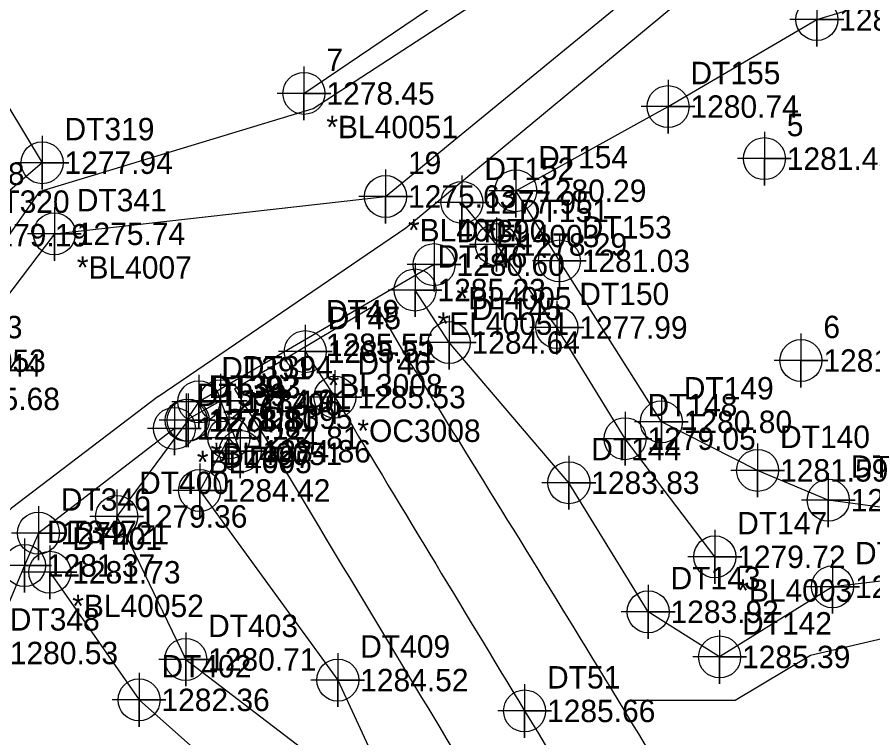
# Model space of a CAD drawing. Extents: x 1394009 to 1394411, y 957864 to 958364.
# Drawn here: x 1394188.2 to 1394283.7, y 958034.4 to 958114.8 of the extents above; entities that cross this region are included whole.
import ezdxf

# ---------------------------------------------------------------- set-up
doc = ezdxf.new("R2010")
doc.units = 0
for name, color, linetype in [('Exist DTM Breakline', 7, 'Continuous'), ('Exist DTM Breakline Cogo Comment', 7, 'Continuous'), ('Exist DTM Breakline Cogo Elevation', 7, 'Continuous'), ('Exist DTM Breakline Cogo Number', 7, 'Continuous'), ('Exist DTM Breakline Cogo Point CELL', 7, 'Continuous'), ('Exist DTM Breakline Underwater', 7, 'Continuous'), ('Exist DTM Breakline Underwater Cogo Comment', 7, 'Continuous'), ('Exist DTM Breakline Underwater Cogo Elevation', 7, 'Continuous'), ('Exist DTM Breakline Underwater Cogo Number', 7, 'Continuous'), ('Exist DTM Breakline Underwater Cogo Point CELL', 7, 'Continuous'), ('Exist DTM Crownline', 7, 'Continuous'), ('Exist DTM Drainline', 7, 'Continuous'), ('Exist DTM Drainline Cogo Comment', 7, 'Continuous'), ('Exist DTM Drainline Cogo Elevation', 7, 'Continuous'), ('Exist DTM Drainline Cogo Number', 7, 'Continuous'), ('Exist DTM Drainline Cogo Point CELL', 7, 'Continuous'), ('Exist DTM Regular Point Cogo Elevation', 7, 'Continuous'), ('Exist Hydro Stream or Body of Water', 7, 'Continuous'), ('Exist Roads EOP', 7, 'Continuous'), ('Exist Roads Soil', 7, 'Continuous'), ('Exist Structure Minor Culvert Topo', 7, 'Continuous'), ('Exist Structure Minor Culvert Topo Terminator', 7, 'Continuous'), ('Exist Structure Minor Footbridge', 7, 'Continuous'), ('Exist Structure Minor Footbridge Terminator', 7, 'Continuous'), ('PH Exist DTM NCFMP LIDAR Elevation Point', 7, 'Continuous'), ('Raster_Level_0', 7, 'Continuous')]:
    doc.layers.add(name, color=color, linetype=linetype)

msp = doc.modelspace()

# ---------------------------------------------------------------- linework, layer by layer
at = {"layer": 'Exist DTM Breakline'}
for points in [[(1394078.4815, 958267.2528), (1394082.9126, 958267.3867), (1394095.8187, 958243.0525), (1394113.4272, 958206.3553), (1394134.4907, 958171.1858), (1394155.1759, 958139.8204), (1394165.1856, 958129.7757), (1394177.2665, 958121.2673), (1394190.9858, 958098.52), (1394181.5225, 958090.4285), (1394174.2125, 958080.1878)], [(1394220.2003, 958106.2482), (1394237.6839, 958118.114), (1394249.3757, 958131.9705), (1394256.7573, 958157.1006), (1394253.8139, 958176.5432), (1394241.3147, 958204.2553), (1394238.5837, 958222.5694)], [(1394338.5703, 958071.7873), (1394311.6428, 958061.939), (1394296.3165, 958058.5038), (1394278.7037, 958060.8799), (1394270.8162, 958064.205), (1394260.0757, 958069.6149), (1394248.6938, 958087.5642), (1394243.8244, 958095.3933), (1394260.8199, 958104.7758), (1394277.4189, 958114.4853), (1394301.9851, 958121.8746)], [(1394234.7161, 958087.1493), (1394208.4745, 958071.86), (1394207.051, 958069.7897), (1394210.8783, 958071.9618), (1394213.0858, 958066.3393), (1394211.818, 958067.823), (1394208.5647, 958061.9703), (1394223.9737, 958040.8216), (1394237.157, 958012.3346), (1394253.5006, 957985.8224), (1394267.2603, 957974.749), (1394288.6525, 957938.4432), (1394308.2436, 957898.2998)], [(1394314.9529, 958057.597), (1394299.8393, 958053.6184), (1394279.177, 958051.2301), (1394266.5791, 958043.3997), (1394258.6023, 958048.4386), (1394249.7488, 958062.8318), (1394236.4026, 958078.4617), (1394232.5982, 958084.3218)], [(1394207.2831, 958069.7981), (1394199.3051, 958059.0705), (1394207.0076, 958043.1259), (1394225.1737, 958029.2554), (1394237.0033, 958012.304)], [(1394205.7466, 958068.8917), (1394190.5711, 958057.2067), (1394189.0222, 958053.5957), (1394184.8806, 958043.8407), (1394186.4655, 958021.4355), (1394191.8774, 958003.2638), (1394213.2872, 957998.1706), (1394228.4733, 957975.4923), (1394239.8888, 957946.4968), (1394241.0497, 957903.4511)], [(1394191.8454, 958052.8419), (1394201.7992, 958038.6118), (1394220.6022, 958021.9205), (1394235.2523, 958009.2773), (1394253.0852, 957986.3641)]]:
    msp.add_lwpolyline(points, dxfattribs=at)
at = {"layer": 'Exist DTM Breakline Cogo Point CELL'}
for points in [[(1394277.4189, 958117.4853), (1394277.4189, 958111.4853), (1394277.4189, 958114.4853), (1394280.4189, 958114.4853), (1394274.4189, 958114.4853)], [(1394220.2003, 958109.2482), (1394220.2003, 958103.2482), (1394220.2003, 958106.2482), (1394223.2003, 958106.2482), (1394217.2003, 958106.2482)], [(1394260.8199, 958107.7758), (1394260.8199, 958101.7758), (1394260.8199, 958104.7758), (1394263.8199, 958104.7758), (1394257.8199, 958104.7758)], [(1394190.9858, 958101.52), (1394190.9858, 958095.52), (1394190.9858, 958098.52), (1394193.9858, 958098.52), (1394187.9858, 958098.52)], [(1394243.8244, 958098.3933), (1394243.8244, 958092.3933), (1394243.8244, 958095.3933), (1394246.8244, 958095.3933), (1394240.8244, 958095.3933)], [(1394234.7161, 958090.1493), (1394234.7161, 958084.1493), (1394234.7161, 958087.1493), (1394237.7161, 958087.1493), (1394231.7161, 958087.1493)], [(1394248.6938, 958090.5642), (1394248.6938, 958084.5642), (1394248.6938, 958087.5642), (1394251.6938, 958087.5642), (1394245.6938, 958087.5642)], [(1394232.5982, 958087.3218), (1394232.5982, 958081.3218), (1394232.5982, 958084.3218), (1394235.5982, 958084.3218), (1394229.5982, 958084.3218)], [(1394236.4026, 958081.4617), (1394236.4026, 958075.4617), (1394236.4026, 958078.4617), (1394239.4026, 958078.4617), (1394233.4026, 958078.4617)], [(1394208.4745, 958074.86), (1394208.4745, 958068.86), (1394208.4745, 958071.86), (1394211.4745, 958071.86), (1394205.4745, 958071.86)], [(1394210.8783, 958074.9618), (1394210.8783, 958068.9618), (1394210.8783, 958071.9618), (1394213.8783, 958071.9618), (1394207.8783, 958071.9618)], [(1394207.051, 958072.7897), (1394207.051, 958066.7897), (1394207.051, 958069.7897), (1394210.051, 958069.7897), (1394204.051, 958069.7897)], [(1394207.2831, 958072.7981), (1394207.2831, 958066.7981), (1394207.2831, 958069.7981), (1394210.2831, 958069.7981), (1394204.2831, 958069.7981)], [(1394260.0757, 958072.6149), (1394260.0757, 958066.6149), (1394260.0757, 958069.6149), (1394263.0757, 958069.6149), (1394257.0757, 958069.6149)], [(1394205.7466, 958071.8917), (1394205.7466, 958065.8917), (1394205.7466, 958068.8917), (1394208.7466, 958068.8917), (1394202.7466, 958068.8917)], [(1394211.818, 958070.823), (1394211.818, 958064.823), (1394211.818, 958067.823), (1394214.818, 958067.823), (1394208.818, 958067.823)], [(1394213.0858, 958069.3393), (1394213.0858, 958063.3393), (1394213.0858, 958066.3393), (1394216.0858, 958066.3393), (1394210.0858, 958066.3393)], [(1394270.8162, 958067.205), (1394270.8162, 958061.205), (1394270.8162, 958064.205), (1394273.8162, 958064.205), (1394267.8162, 958064.205)], [(1394249.7488, 958065.8318), (1394249.7488, 958059.8318), (1394249.7488, 958062.8318), (1394252.7488, 958062.8318), (1394246.7488, 958062.8318)], [(1394208.5647, 958064.9703), (1394208.5647, 958058.9703), (1394208.5647, 958061.9703), (1394211.5647, 958061.9703), (1394205.5647, 958061.9703)], [(1394278.7037, 958063.8799), (1394278.7037, 958057.8799), (1394278.7037, 958060.8799), (1394281.7037, 958060.8799), (1394275.7037, 958060.8799)], [(1394199.3051, 958062.0705), (1394199.3051, 958056.0705), (1394199.3051, 958059.0705), (1394202.3051, 958059.0705), (1394196.3051, 958059.0705)], [(1394190.5711, 958060.2067), (1394190.5711, 958054.2067), (1394190.5711, 958057.2067), (1394193.5711, 958057.2067), (1394187.5711, 958057.2067)], [(1394189.0222, 958056.5957), (1394189.0222, 958050.5957), (1394189.0222, 958053.5957), (1394192.0222, 958053.5957), (1394186.0222, 958053.5957)], [(1394191.8454, 958055.8419), (1394191.8454, 958049.8419), (1394191.8454, 958052.8419), (1394194.8454, 958052.8419), (1394188.8454, 958052.8419)], [(1394279.177, 958054.2301), (1394279.177, 958048.2301), (1394279.177, 958051.2301), (1394282.177, 958051.2301), (1394276.177, 958051.2301)], [(1394258.6023, 958051.4386), (1394258.6023, 958045.4386), (1394258.6023, 958048.4386), (1394261.6023, 958048.4386), (1394255.6023, 958048.4386)], [(1394207.0076, 958046.1259), (1394207.0076, 958040.1259), (1394207.0076, 958043.1259), (1394210.0076, 958043.1259), (1394204.0076, 958043.1259)], [(1394266.5791, 958046.3997), (1394266.5791, 958040.3997), (1394266.5791, 958043.3997), (1394269.5791, 958043.3997), (1394263.5791, 958043.3997)], [(1394223.9737, 958043.8216), (1394223.9737, 958037.8216), (1394223.9737, 958040.8216), (1394226.9737, 958040.8216), (1394220.9737, 958040.8216)], [(1394201.7992, 958041.6118), (1394201.7992, 958035.6118), (1394201.7992, 958038.6118), (1394204.7992, 958038.6118), (1394198.7992, 958038.6118)]]:
    msp.add_lwpolyline(points, dxfattribs=at)
for centre in [(1394277.4189, 958114.4853), (1394220.2003, 958106.2482), (1394260.8199, 958104.7758), (1394190.9858, 958098.52), (1394243.8244, 958095.3933), (1394248.6938, 958087.5642), (1394234.7161, 958087.1493), (1394232.5982, 958084.3218), (1394236.4026, 958078.4617), (1394208.4745, 958071.86), (1394210.8783, 958071.9618), (1394207.051, 958069.7897), (1394207.2831, 958069.7981), (1394260.0757, 958069.6149), (1394205.7466, 958068.8917), (1394211.818, 958067.823), (1394213.0858, 958066.3393), (1394270.8162, 958064.205), (1394249.7488, 958062.8318), (1394208.5647, 958061.9703), (1394278.7037, 958060.8799), (1394199.3051, 958059.0705), (1394190.5711, 958057.2067), (1394189.0222, 958053.5957), (1394191.8454, 958052.8419), (1394279.177, 958051.2301), (1394258.6023, 958048.4386), (1394266.5791, 958043.3997), (1394207.0076, 958043.1259), (1394223.9737, 958040.8216), (1394201.7992, 958038.6118)]:
    msp.add_circle(centre, 2.344, dxfattribs=at)
at = {"layer": 'Exist DTM Breakline Underwater'}
for points in [[(1394229.3063, 958094.7507), (1394267.6222, 958126.159), (1394273.9153, 958153.4417), (1394270.8807, 958172.7151), (1394257.7841, 958202.8194), (1394247.0365, 958219.368), (1394259.7999, 958250.0935), (1394260.5275, 958261.5147), (1394243.0302, 958273.0023), (1394215.1121, 958260.9873), (1394175.4465, 958249.379), (1394164.3967, 958267.5944), (1394161.8631, 958300.0699), (1394178.2103, 958310.6665)], [(1394192.3583, 958090.5901), (1394229.3063, 958094.7507)], [(1394192.3583, 958090.5901), (1394178.3868, 958072.1738), (1394169.2021, 958057.4892), (1394167.6851, 958038.5052), (1394159.1429, 958013.4636), (1394180.3464, 957994.6406), (1394199.7643, 957985.953), (1394224.0434, 957972.821), (1394228.1265, 957943.556), (1394220.9394, 957914.628)]]:
    msp.add_lwpolyline(points, dxfattribs=at)
at = {"layer": 'Exist DTM Breakline Underwater Cogo Point CELL'}
for points in [[(1394229.3063, 958097.7507), (1394229.3063, 958091.7507), (1394229.3063, 958094.7507), (1394232.3063, 958094.7507), (1394226.3063, 958094.7507)], [(1394192.3583, 958093.5901), (1394192.3583, 958087.5901), (1394192.3583, 958090.5901), (1394195.3583, 958090.5901), (1394189.3583, 958090.5901)]]:
    msp.add_lwpolyline(points, dxfattribs=at)
for centre in [(1394229.3063, 958094.7507), (1394192.3583, 958090.5901)]:
    msp.add_circle(centre, 2.344, dxfattribs=at)
at = {"layer": 'Exist DTM Crownline'}
msp.add_line((1394220.3484, 958077.4466), (1394223.6604, 958072.3799), dxfattribs=at)
msp.add_spline([(1394223.6604, 958072.3799), (1394244.8218, 958037.3795), (1394269.4506, 957997.0996), (1394294.4399, 957957.1952), (1394318.0033, 957919.003)], degree=3, dxfattribs=at)
at = {"layer": 'Exist DTM Drainline'}
msp.add_lwpolyline([(1394266.0362, 958054.5678), (1394256.024, 958067.7418), (1394248.4193, 958080.134), (1394241.6733, 958089.3993), (1394237.8268, 958094.0923)], dxfattribs=at)
at = {"layer": 'Exist DTM Drainline Cogo Point CELL'}
for points in [[(1394237.8268, 958097.0923), (1394237.8268, 958091.0923), (1394237.8268, 958094.0923), (1394240.8268, 958094.0923), (1394234.8268, 958094.0923)], [(1394241.6733, 958092.3993), (1394241.6733, 958086.3993), (1394241.6733, 958089.3993), (1394244.6733, 958089.3993), (1394238.6733, 958089.3993)], [(1394248.4193, 958083.134), (1394248.4193, 958077.134), (1394248.4193, 958080.134), (1394251.4193, 958080.134), (1394245.4193, 958080.134)], [(1394256.024, 958070.7418), (1394256.024, 958064.7418), (1394256.024, 958067.7418), (1394259.024, 958067.7418), (1394253.024, 958067.7418)], [(1394266.0362, 958057.5678), (1394266.0362, 958051.5678), (1394266.0362, 958054.5678), (1394269.0362, 958054.5678), (1394263.0362, 958054.5678)]]:
    msp.add_lwpolyline(points, dxfattribs=at)
for centre in [(1394237.8268, 958094.0923), (1394241.6733, 958089.3993), (1394248.4193, 958080.134), (1394256.024, 958067.7418), (1394266.0362, 958054.5678)]:
    msp.add_circle(centre, 2.344, dxfattribs=at)
at = {"layer": 'Exist Hydro Stream or Body of Water'}
for points in [[(1394221.231, 958104.5797), (1394238.8971, 958116.0346), (1394254.7004, 958129.0614), (1394261.0998, 958155.6228), (1394258.5223, 958177.5159), (1394245.4045, 958205.4301), (1394241.5211, 958222.9502), (1394246.6022, 958237.6666), (1394253.5489, 958252.431), (1394251.9663, 958257.7082), (1394245.398, 958262.4184), (1394226.1093, 958259.8812), (1394198.4822, 958248.5108), (1394177.4215, 958243.2011), (1394168.9777, 958246.0581), (1394155.8669, 958264.1507), (1394149.2709, 958283.1502), (1394154.661, 958297.4554), (1394160.3871, 958316.4078), (1394173.556, 958323.8378)], [(1394231.5705, 958091.2594), (1394270.5171, 958123.5077), (1394277.8383, 958154.0025), (1394278.608, 958197.1243), (1394267.0972, 958226.2539), (1394275.5986, 958257.1902), (1394265.6306, 958269.8313), (1394243.4303, 958275.2121), (1394210.2309, 958270.0539), (1394177.5999, 958260.6264), (1394172.1027, 958270.6648), (1394169.7578, 958290.7959), (1394182.6519, 958307.5361)], [(1394190.7058, 958095.3239), (1394221.231, 958104.5797)], [(1394190.7058, 958095.3239), (1394177.2279, 958076.1665), (1394160.3309, 958063.4331), (1394156.4808, 958036.0172), (1394151.8807, 958011.6814), (1394172.2345, 957982.059), (1394181.0188, 957978.4843), (1394196.9657, 957983.1686), (1394210.7106, 957964.4319), (1394215.4703, 957941.598), (1394209.5541, 957917.1532)], [(1394203.9517, 958072.4517), (1394231.5705, 958091.2594)], [(1394203.9517, 958072.4517), (1394187.582, 958060.0115), (1394178.1893, 958051.3287), (1394177.8231, 958039.3974), (1394183.6296, 958020.3053), (1394189.4903, 958000.9486), (1394211.9273, 957995.783), (1394226.7784, 957973.5412), (1394236.5763, 957945.2073), (1394231.9355, 957908.562)]]:
    msp.add_lwpolyline(points, dxfattribs=at)
at = {"layer": 'Exist Roads EOP'}
for p, q in [((1394228.2198, 958082.6512), (1394231.4675, 958077.1435)), ((1394212.4573, 958073.2677), (1394215.8384, 958067.9044))]:
    msp.add_line(p, q, dxfattribs=at)
msp.add_lwpolyline([(1394228.2198, 958082.6512), (1394212.4573, 958073.2677)], dxfattribs=at)
for points in [[(1394231.4675, 958077.1435), (1394252.9816, 958042.2643), (1394277.1668, 958002.5538), (1394302.3527, 957962.1709), (1394325.7525, 957924.4929)], [(1394215.8384, 958067.9044), (1394237.3577, 958032.1628), (1394261.7049, 957991.7458), (1394286.4849, 957951.9331), (1394310.1777, 957914.0367)]]:
    msp.add_spline(points, degree=3, dxfattribs=at)
at = {"layer": 'Exist Roads Soil'}
msp.add_lwpolyline([(1394340.5459, 958062.5087), (1394308.3278, 958051.9593), (1394285.3476, 958045.5699), (1394276.7186, 958043.5458), (1394268.3214, 958038.5621), (1394256.6207, 958038.5618)], dxfattribs=at)
at = {"layer": 'Exist Structure Minor Culvert Topo Terminator'}
for points in [[(1394220.3484, 958080.4466), (1394220.3484, 958074.4466), (1394220.3484, 958077.4466), (1394223.3484, 958077.4466), (1394217.3484, 958077.4466)], [(1394223.6604, 958075.3799), (1394223.6604, 958069.3799), (1394223.6604, 958072.3799), (1394226.6604, 958072.3799), (1394220.6604, 958072.3799)], [(1394244.8218, 958040.3795), (1394244.8218, 958034.3795), (1394244.8218, 958037.3795), (1394247.8218, 958037.3795), (1394241.8218, 958037.3795)]]:
    msp.add_lwpolyline(points, dxfattribs=at)
for centre in [(1394220.3484, 958077.4466), (1394223.6604, 958072.3799), (1394244.8218, 958037.3795)]:
    msp.add_circle(centre, 2.344, dxfattribs=at)
at = {"layer": 'PH Exist DTM NCFMP LIDAR Elevation Point'}
for points in [[(1394271.5694, 958101.9727), (1394271.5694, 958095.9727), (1394271.5694, 958098.9727), (1394274.5694, 958098.9727), (1394268.5694, 958098.9727)], [(1394275.6526, 958079.4543), (1394275.6526, 958073.4543), (1394275.6526, 958076.4543), (1394278.6526, 958076.4543), (1394272.6526, 958076.4543)]]:
    msp.add_lwpolyline(points, dxfattribs=at)
for centre in [(1394271.5694, 958098.9727), (1394275.6526, 958076.4543)]:
    msp.add_circle(centre, 2.344, dxfattribs=at)

# ---------------------------------------------------------------- texts
at = {"layer": 'Exist DTM Breakline Cogo Comment'}
for s, p in [('*BL40051', (1394222.7003, 958101.2482)), ('*BL4005', (1394237.2161, 958082.1493)), ('*EL40051', (1394235.0982, 958079.3218)), ('*EL40053', (1394176.7125, 958075.1878)), ('*BL40051', (1394209.7831, 958064.7981)), ('*BL4005', (1394208.2466, 958063.8917)), ('*BL40052', (1394194.3454, 958047.8419))]:
    msp.add_text(s, height=2.5, dxfattribs=at).set_placement(p)
at = {"layer": 'Exist DTM Breakline Cogo Elevation'}
for s, p in [('1280.37', (1394279.9189, 958113.2353)), ('1278.45', (1394222.7003, 958104.9982)), ('1280.74', (1394263.3199, 958103.5258)), ('1277.94', (1394193.4858, 958097.27)), ('1280.29', (1394246.3244, 958094.1433)), ('1279.19', (1394184.0225, 958089.1785)), ('1281.03', (1394251.1938, 958086.3142)), ('1280.60', (1394237.2161, 958085.8993)), ('1285.23', (1394235.0982, 958083.0718)), ('1278.53', (1394176.7125, 958078.9378)), ('1284.64', (1394238.9026, 958077.2117)), ('1277.47', (1394210.9745, 958070.61)), ('1284.91', (1394213.3783, 958070.7118)), ('1278.81', (1394209.551, 958068.5397)), ('1278.80', (1394209.7831, 958068.5481)), ('1280.80', (1394262.5757, 958068.3649)), ('1279.12', (1394208.2466, 958067.6417)), ('1284.81', (1394214.318, 958066.573)), ('1284.86', (1394215.5858, 958065.0893)), ('1281.59', (1394273.3162, 958062.955)), ('1283.83', (1394252.2488, 958061.5818)), ('1284.42', (1394211.0647, 958060.7203)), ('1282.39', (1394281.2037, 958059.6299)), ('1279.36', (1394201.8051, 958057.8205)), ('1279.21', (1394193.0711, 958055.9567)), ('1281.37', (1394191.5222, 958052.3457)), ('1281.73', (1394194.3454, 958051.5919)), ('1284.58', (1394281.677, 958049.9801)), ('1283.92', (1394261.1023, 958047.1886)), ('1280.53', (1394187.3806, 958042.5907)), ('1280.71', (1394209.5076, 958041.8759)), ('1285.39', (1394269.0791, 958042.1497)), ('1284.52', (1394226.4737, 958039.5716)), ('1282.36', (1394204.2992, 958037.3618))]:
    msp.add_text(s, height=2.5, dxfattribs=at).set_placement(p)
at = {"layer": 'Exist DTM Breakline Cogo Number'}
for s, p in [('7', (1394222.7003, 958108.7482)), ('DT155', (1394263.3199, 958107.2758)), ('DT319', (1394193.4858, 958101.02)), ('DT154', (1394246.3244, 958097.8933)), ('DT320', (1394184.0225, 958092.9285)), ('DT153', (1394251.1938, 958090.0642)), ('DT390', (1394237.2161, 958089.6493)), ('DT146', (1394235.0982, 958086.8218)), ('DT145', (1394238.9026, 958080.9617)), ('DT391', (1394210.9745, 958074.36)), ('DT394', (1394213.3783, 958074.4618)), ('DT392', (1394209.551, 958072.2897)), ('DT393', (1394209.7831, 958072.2981)), ('DT149', (1394262.5757, 958072.1149)), ('DT339', (1394208.2466, 958071.3917)), ('DT396', (1394214.318, 958070.323)), ('DT395', (1394215.5858, 958068.8393)), ('DT140', (1394273.3162, 958066.705)), ('DT144', (1394252.2488, 958065.3318)), ('DT397', (1394211.0647, 958064.4703)), ('DT139', (1394281.2037, 958063.3799)), ('DT400', (1394201.8051, 958061.5705)), ('DT346', (1394193.0711, 958059.7067)), ('DT347', (1394191.5222, 958056.0957)), ('DT401', (1394194.3454, 958055.3419)), ('DT141', (1394281.677, 958053.7301)), ('DT143', (1394261.1023, 958050.9386)), ('DT348', (1394187.3806, 958046.3407)), ('DT403', (1394209.5076, 958045.6259)), ('DT142', (1394269.0791, 958045.8997)), ('DT409', (1394226.4737, 958043.3216)), ('DT402', (1394204.2992, 958041.1118))]:
    msp.add_text(s, height=2.5, dxfattribs=at).set_placement(p)
at = {"layer": 'Exist DTM Breakline Underwater Cogo Comment'}
for p in [(1394231.8063, 958089.7507), (1394194.8583, 958085.5901)]:
    msp.add_text('*BL4007', height=2.5, dxfattribs=at).set_placement(p)
at = {"layer": 'Exist DTM Breakline Underwater Cogo Elevation'}
for s, p in [('1275.63', (1394231.8063, 958093.5007)), ('1275.74', (1394194.8583, 958089.3401)), ('1275.68', (1394180.8868, 958070.9238))]:
    msp.add_text(s, height=2.5, dxfattribs=at).set_placement(p)
at = {"layer": 'Exist DTM Breakline Underwater Cogo Number'}
for s, p in [('19', (1394231.8063, 958097.2507)), ('DT341', (1394194.8583, 958093.0901)), ('DT344', (1394180.8868, 958074.6738))]:
    msp.add_text(s, height=2.5, dxfattribs=at).set_placement(p)
at = {"layer": 'Exist DTM Drainline Cogo Comment'}
for s, p in [('*EL4003', (1394240.3268, 958089.0923)), ('*BL4003', (1394268.5362, 958049.5678))]:
    msp.add_text(s, height=2.5, dxfattribs=at).set_placement(p)
at = {"layer": 'Exist DTM Drainline Cogo Elevation'}
for s, p in [('1277.95', (1394240.3268, 958092.8423)), ('1278.29', (1394244.1733, 958088.1493)), ('1277.99', (1394250.9193, 958078.884)), ('1279.05', (1394258.524, 958066.4918)), ('1279.72', (1394268.5362, 958053.3178))]:
    msp.add_text(s, height=2.5, dxfattribs=at).set_placement(p)
at = {"layer": 'Exist DTM Drainline Cogo Number'}
for s, p in [('DT152', (1394240.3268, 958096.5923)), ('DT151', (1394244.1733, 958091.8993)), ('DT150', (1394250.9193, 958082.634)), ('DT148', (1394258.524, 958070.2418)), ('DT147', (1394268.5362, 958057.0678))]:
    msp.add_text(s, height=2.5, dxfattribs=at).set_placement(p)
at = {"layer": 'Exist DTM Regular Point Cogo Elevation'}
for s, p in [('1281.45', (1394274.0694, 958097.7227)), ('1278.28', (1394176.9403, 958096.0297)), ('1285.55', (1394222.643, 958076.9662)), ('1281.85', (1394278.1526, 958075.2043))]:
    msp.add_text(s, height=2.5, dxfattribs=at).set_placement(p)
at = {"layer": 'Exist Structure Minor Culvert Topo'}
for s, p in [('DT45', (1394222.8484, 958079.9466)), ('DT46', (1394226.1604, 958074.8799)), ('DT51', (1394247.3218, 958039.8795))]:
    msp.add_text(s, height=2.5, dxfattribs=at).set_placement(p)
at = {"layer": 'Exist Structure Minor Footbridge'}
for s, p in [('*BL3008', (1394222.8484, 958072.4466)), ('*OC3008', (1394226.1604, 958067.3799))]:
    msp.add_text(s, height=2.5, dxfattribs=at).set_placement(p)
at = {"layer": 'Exist Structure Minor Footbridge Terminator'}
for s, p in [('1285.51', (1394222.8484, 958076.1966)), ('1285.53', (1394226.1604, 958071.1299)), ('1285.66', (1394247.3218, 958036.1295))]:
    msp.add_text(s, height=2.5, dxfattribs=at).set_placement(p)
at = {"layer": 'Raster_Level_0'}
for s, p in [('5', (1394274.0694, 958101.4727)), ('DT49', (1394222.643, 958080.7162)), ('6', (1394278.1526, 958078.9543))]:
    msp.add_text(s, height=2.5, dxfattribs=at).set_placement(p)

doc.saveas('drawing.dxf')
